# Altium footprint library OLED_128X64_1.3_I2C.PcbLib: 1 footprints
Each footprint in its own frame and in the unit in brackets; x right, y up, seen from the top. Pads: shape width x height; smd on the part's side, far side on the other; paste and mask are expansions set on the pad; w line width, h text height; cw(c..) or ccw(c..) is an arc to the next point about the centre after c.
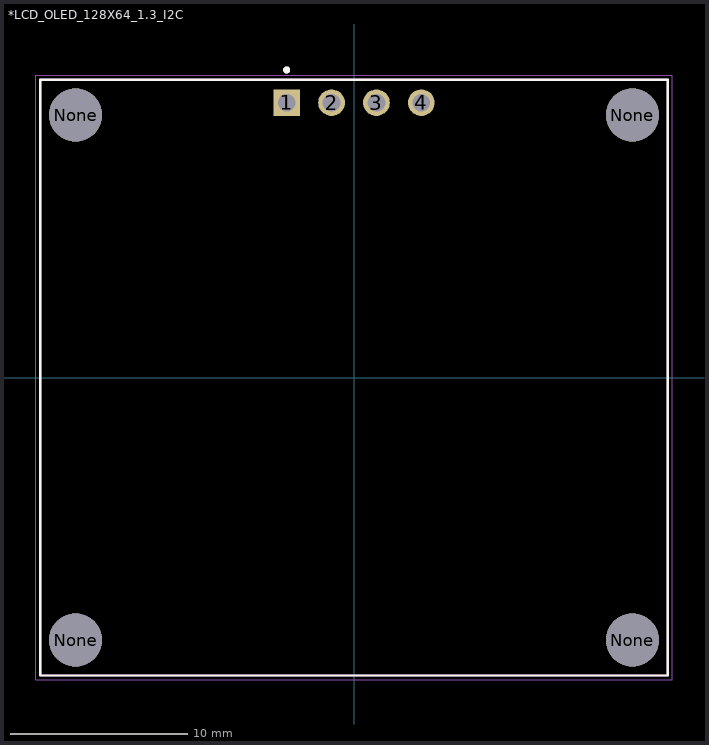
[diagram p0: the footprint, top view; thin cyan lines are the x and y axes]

## *LCD_OLED_128X64_1.3_I2C [mm]
pads (8):
  rect 1.508x1.508 hole 1: 1(-3.81,15.55)
  round 1.508 hole 1: 2(-1.27,15.55) 3(1.27,15.55) 4(3.81,15.55)
  round 3 hole 3 unplated: None(-15.75,-14.85) None(-15.75,14.85) None(15.75,-14.85) None(15.75,14.85)
Top Overlay:
  circle w0.2: c-3.81,17.4 r0.1
  lines w0.127: -17.75,-16.85 -17.75,16.85 17.75,16.85 17.75,-16.85 -17.75,-16.85
Mechanical 4:
  circle w0.2: c-3.81,17.4 r0.1
  circle w0.2: c-3.81,17.4 r0.1
  lines w0.127: -17.75,-16.85 -17.75,16.85 ; -17.75,-16.85 17.75,-16.85 ; -17.75,-16.85 -17.75,16.85 ; -17.75,-16.85 17.75,-16.85 ; -17.75,16.85 17.75,16.85 ; -17.75,16.85 17.75,16.85 ; 17.75,-16.85 17.75,16.85 ; 17.75,-16.85 17.75,16.85
Mechanical 16:
  lines w0.05: -18,-17.1 18,-17.1 18,17.1 -18,17.1 -18,-17.1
